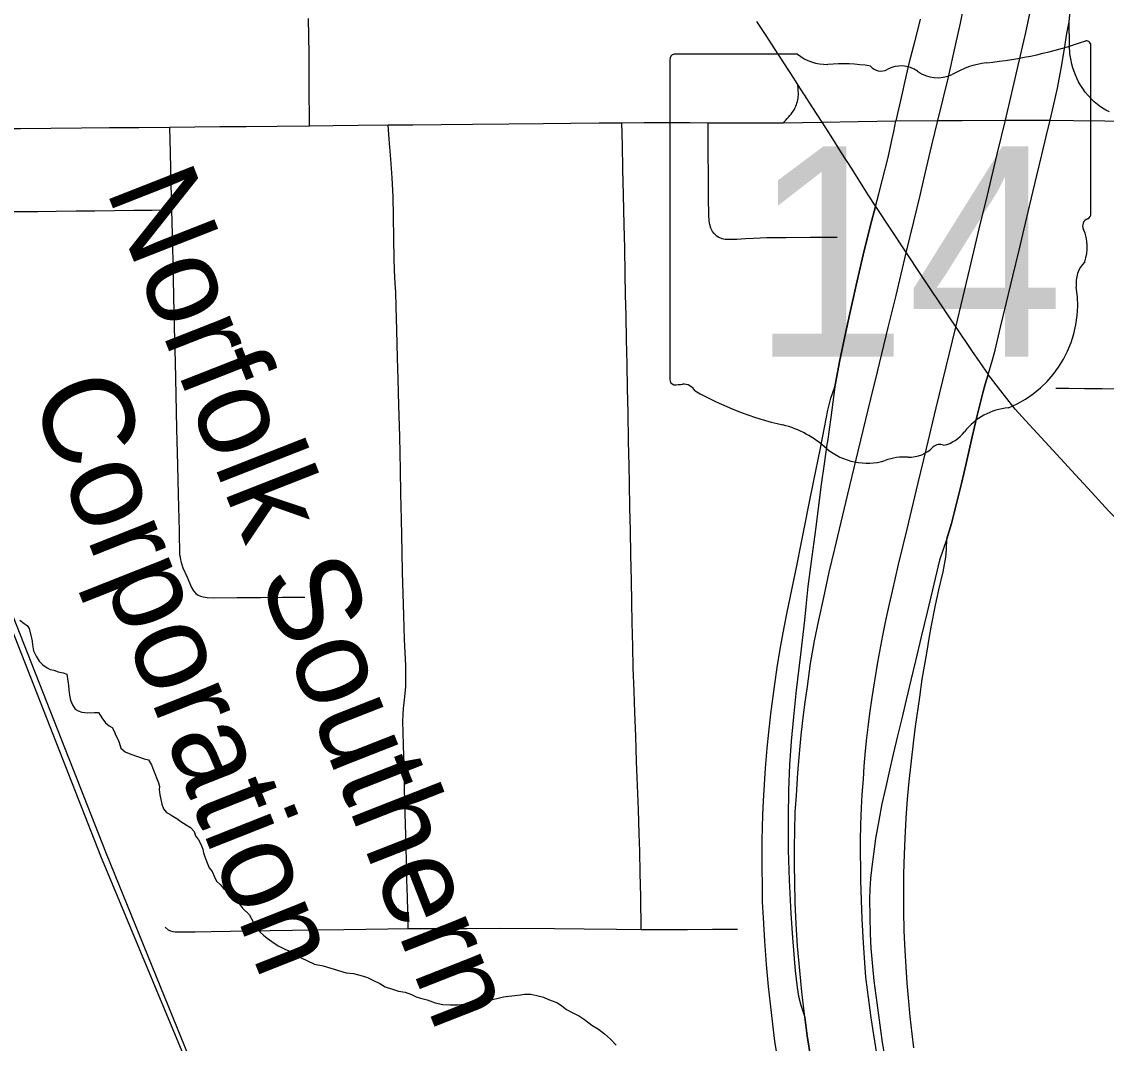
# Model space of a CAD drawing. Extents: x 0 to 34, y 0 to 22.
# Drawn here: x 4.679 to 5.359, y 16.317 to 16.957 of the extents above; entities that cross this region are included whole.
import ezdxf

# ---------------------------------------------------------------- set-up
doc = ezdxf.new("R2010")
doc.units = 0
for name, color, linetype in [('GM_X_City_Street', 7, 'Continuous'), ('GM_X_County_Road', 7, 'Continuous'), ('GM_X_Interchange_Ramps', 7, 'Continuous'), ('GM_X_Interstate_Route', 7, 'Continuous'), ('GM_X_Minor_River', 7, 'Continuous'), ('GM_X_Rail_Line', 7, 'Continuous'), ('GM_X_Rail_Line_Text', 7, 'Continuous'), ('GM_X_State_Location', 7, 'Continuous'), ('GM_X_State_Route', 7, 'Continuous'), ('GM_X_State_Shield', 7, 'Continuous')]:
    doc.layers.add(name, color=color, linetype=linetype)

msp = doc.modelspace()

# ---------------------------------------------------------------- linework, layer by layer
at = {"layer": 'GM_X_City_Street'}
for points in [[(4.85961, 16.892), (4.85946, 16.91777), (4.85928, 16.93707), (4.85899, 16.9591)], [(4.77844, 16.62273), (4.77808, 16.63813), (4.77755, 16.66072), (4.77711, 16.67929), (4.77657, 16.70219), (4.77608, 16.72351), (4.7756, 16.74388), (4.77509, 16.76552), (4.77463, 16.78504), (4.77411, 16.80709), (4.77372, 16.82388), (4.77336, 16.83936), (4.77296, 16.85565), (4.7725, 16.87506), (4.77212, 16.89111)], [(4.92138, 16.38902), (4.92111, 16.39977), (4.92089, 16.40863), (4.92061, 16.41963), (4.92036, 16.42948), (4.92005, 16.44149), (4.91973, 16.45434), (4.9194, 16.46773), (4.91913, 16.47813), (4.91879, 16.49176), (4.91848, 16.50384), (4.91827, 16.51213), (4.9181, 16.51875), (4.91818, 16.5233), (4.91841, 16.52691), (4.91879, 16.53054), (4.91949, 16.53631), (4.91987, 16.54061), (4.92003, 16.54308), (4.91987, 16.55386), (4.9191, 16.5701), (4.91864, 16.58511), (4.91826, 16.59896), (4.91787, 16.61213), (4.91756, 16.62498), (4.91715, 16.64561), (4.91689, 16.66139), (4.91664, 16.6764), (4.91608, 16.69726), (4.91553, 16.71665), (4.91507, 16.73313), (4.91469, 16.74667), (4.9142, 16.76399), (4.91392, 16.77862), (4.91361, 16.78763), (4.91331, 16.79324), (4.91292, 16.80133), (4.91271, 16.80902), (4.91247, 16.82096), (4.91216, 16.83565), (4.91192, 16.84735), (4.91131, 16.85936), (4.91054, 16.87098), (4.90957, 16.88361), (4.90889, 16.89249)], [(5.05672, 16.82998), (5.0563, 16.8486), (5.05592, 16.86468), (5.05557, 16.87983), (5.05525, 16.89386)], [(5.11425, 16.82315), (5.11297, 16.82444), (5.11209, 16.82565), (5.11098, 16.82778), (5.11024, 16.83006), (5.1099, 16.83243), (5.1097, 16.83588), (5.1096, 16.84691), (5.10949, 16.86102), (5.10937, 16.8748), (5.10929, 16.8849), (5.10921, 16.89391)], [(4.65945, 16.84522), (4.66116, 16.84357), (4.66256, 16.84246), (4.66455, 16.84116), (4.66614, 16.84033), (4.66778, 16.83964), (4.67005, 16.83892), (4.67238, 16.83844), (4.67475, 16.83823), (4.6894, 16.83831), (4.70088, 16.83846), (4.71347, 16.83861), (4.72509, 16.83875), (4.73754, 16.83891), (4.74961, 16.83906), (4.76101, 16.8392), (4.77336, 16.83936)], [(5.06729, 16.38837), (5.06716, 16.40913), (5.0668, 16.42372), (5.06646, 16.43762), (5.06611, 16.44837), (5.06556, 16.46374), (5.06502, 16.47868), (5.06447, 16.4938), (5.0639, 16.50962), (5.06336, 16.52447), (5.06288, 16.53775), (5.06236, 16.55243), (5.06207, 16.5658), (5.06175, 16.58083), (5.0615, 16.59333), (5.06121, 16.60739), (5.06089, 16.62303), (5.06058, 16.63859), (5.0603, 16.65257), (5.05999, 16.66812), (5.05977, 16.67886), (5.05946, 16.69433), (5.05909, 16.71242), (5.05879, 16.72719), (5.05848, 16.74283), (5.05818, 16.75794), (5.05787, 16.77306), (5.05761, 16.78608), (5.05735, 16.79928), (5.05702, 16.81526), (5.05672, 16.82998)], [(5.11425, 16.82315), (5.11594, 16.82208), (5.11788, 16.82131), (5.11994, 16.82091), (5.1222, 16.82083), (5.12722, 16.82103), (5.13257, 16.82129), (5.13772, 16.82156), (5.14608, 16.8219), (5.15785, 16.82198), (5.17323, 16.8221), (5.19016, 16.82223)], [(5.32708, 16.7276), (5.33521, 16.72751), (5.34491, 16.72741), (5.35616, 16.72729), (5.36721, 16.72717), (5.38138, 16.72703), (5.39772, 16.72685), (5.40803, 16.72698), (5.42057, 16.72712), (5.43305, 16.72727), (5.44573, 16.72742), (5.45746, 16.72756), (5.46798, 16.72768)], [(4.77844, 16.62273), (4.77874, 16.62012), (4.77913, 16.6183), (4.78031, 16.61497), (4.78294, 16.60912), (4.78578, 16.60278), (4.78704, 16.60073), (4.7884, 16.59903), (4.78982, 16.59795), (4.79124, 16.59724), (4.79298, 16.59677), (4.79559, 16.59645), (4.79963, 16.59629), (4.81411, 16.59639), (4.82884, 16.59648), (4.84245, 16.59657), (4.85677, 16.59661)], [(4.76921, 16.38999), (4.77114, 16.38822), (4.77255, 16.38753), (4.7739, 16.38718), (4.7755, 16.38695), (4.78801, 16.38704), (4.79802, 16.38719), (4.80985, 16.38737), (4.82308, 16.38756), (4.83491, 16.38774), (4.8489, 16.38795), (4.86317, 16.38816), (4.88109, 16.38843), (4.8948, 16.38863), (4.90857, 16.38884), (4.92138, 16.38902), (4.9406, 16.38909), (4.95829, 16.38916), (4.97831, 16.38922), (5.01304, 16.38912), (5.03168, 16.38886), (5.05192, 16.38858), (5.06729, 16.38837), (5.08164, 16.38845), (5.09631, 16.38853), (5.11209, 16.38862), (5.12762, 16.38871)]]:
    msp.add_lwpolyline(points, dxfattribs=at)
at = {"layer": 'GM_X_County_Road'}
for p, q in [((5.1114, 16.8939), (5.11249, 16.8939)), ((5.11249, 16.8939), (5.12712, 16.89388))]:
    msp.add_line(p, q, dxfattribs=at)
for points in [[(5.15618, 16.89385), (5.15799, 16.89555), (5.15886, 16.89645), (5.15969, 16.89737), (5.16049, 16.89833), (5.16126, 16.89931), (5.162, 16.90032), (5.1627, 16.90134), (5.16336, 16.9024), (5.1638, 16.90333), (5.1642, 16.90428), (5.16456, 16.90523), (5.16487, 16.90621), (5.16515, 16.9072), (5.16539, 16.9082), (5.16559, 16.9092), (5.16575, 16.91022), (5.16586, 16.91124), (5.16571, 16.91526), (5.16555, 16.91737)], [(5.1804, 16.8943), (5.20329, 16.89471), (5.22687, 16.89513), (5.25307, 16.8952), (5.26828, 16.8953), (5.29545, 16.89551), (5.3235, 16.89553), (5.3382, 16.89533), (5.3578, 16.89506), (5.37398, 16.89481)], [(5.21401, 16.84149), (5.21616, 16.84931), (5.21857, 16.85836), (5.22197, 16.87201), (5.22418, 16.88184), (5.22554, 16.88831), (5.22687, 16.89513)], [(5.28468, 16.7362), (5.28735, 16.74524), (5.28901, 16.7514), (5.29247, 16.76585), (5.29615, 16.78123), (5.30008, 16.79766), (5.30401, 16.81407), (5.30802, 16.83085), (5.31185, 16.84683), (5.31517, 16.86071), (5.3183, 16.87382), (5.32105, 16.8853), (5.3235, 16.89553)], [(4.63693, 16.88997), (4.64922, 16.89007), (4.66181, 16.89018), (4.67854, 16.89032), (4.69758, 16.89048), (4.71681, 16.89064), (4.7343, 16.89079), (4.75276, 16.89095), (4.77212, 16.89111), (4.78785, 16.89127), (4.80333, 16.89143), (4.81996, 16.8916), (4.83939, 16.89179), (4.85961, 16.892), (4.87448, 16.89215), (4.89015, 16.8923), (4.90889, 16.89249), (4.92428, 16.89263), (4.94206, 16.89278), (4.96177, 16.89295), (4.98437, 16.89315), (5.00615, 16.89333)], [(5.00615, 16.89333), (5.02331, 16.89352), (5.04109, 16.89371), (5.05525, 16.89386)], [(5.05525, 16.89386), (5.06926, 16.89395), (5.08426, 16.89405)], [(5.08426, 16.89405), (5.09792, 16.89397), (5.10921, 16.89391), (5.1114, 16.8939)], [(5.12712, 16.89388), (5.15618, 16.89385), (5.16829, 16.89408), (5.1804, 16.8943)], [(5.18872, 16.72834), (5.19154, 16.74411), (5.19491, 16.75995), (5.19804, 16.77434), (5.20193, 16.79218), (5.20642, 16.81118), (5.21091, 16.82971), (5.21401, 16.84149)], [(5.25874, 16.6331), (5.2617, 16.64275), (5.2649, 16.65533), (5.26786, 16.66782), (5.27082, 16.68042), (5.2747, 16.69703), (5.27762, 16.7096), (5.28128, 16.72462), (5.28287, 16.73019), (5.28468, 16.7362)], [(5.44332, 16.56415), (5.43321, 16.57486), (5.4175, 16.59153), (5.40615, 16.60347), (5.39451, 16.61552), (5.38365, 16.62677), (5.372, 16.63862), (5.36031, 16.65053), (5.34928, 16.66254), (5.33941, 16.67327), (5.32989, 16.68363), (5.32033, 16.69402), (5.31032, 16.70491), (5.30153, 16.71447), (5.29257, 16.72602), (5.28468, 16.7362)], [(5.1522, 16.31083), (5.1511, 16.31853), (5.14981, 16.32919), (5.14823, 16.34183), (5.1471, 16.35282), (5.1458, 16.36658), (5.1447, 16.38107), (5.14385, 16.39574), (5.1434, 16.40585), (5.14327, 16.41411), (5.14313, 16.42878), (5.14319, 16.44452), (5.14352, 16.46023), (5.14387, 16.46912), (5.14449, 16.47932), (5.14522, 16.48962), (5.14627, 16.50212), (5.14722, 16.51212), (5.14851, 16.52351), (5.15076, 16.54073), (5.15271, 16.5541), (5.15483, 16.56644), (5.15686, 16.57769), (5.15878, 16.58734), (5.16161, 16.60133), (5.16493, 16.61737), (5.16726, 16.62907), (5.16962, 16.64053), (5.17258, 16.65527), (5.17547, 16.66965), (5.17936, 16.68887), (5.18212, 16.7029), (5.18424, 16.71373), (5.18619, 16.72133), (5.18872, 16.72834)], [(5.24794, 16.57212), (5.2489, 16.57787), (5.25161, 16.59159), (5.25384, 16.60132), (5.25638, 16.61253), (5.25815, 16.62168), (5.25865, 16.62651), (5.25874, 16.6331)], [(5.23816, 16.31434), (5.23713, 16.32318), (5.2358, 16.33407), (5.23477, 16.34558), (5.23399, 16.35482), (5.23324, 16.36511), (5.23264, 16.37535), (5.23213, 16.38766), (5.23183, 16.40023), (5.23174, 16.41125), (5.23188, 16.42341), (5.23232, 16.43575), (5.23259, 16.44558), (5.23333, 16.45815), (5.23418, 16.47018), (5.2352, 16.48109), (5.23784, 16.50521), (5.23916, 16.51562), (5.24176, 16.53411), (5.24342, 16.54519), (5.24619, 16.56159), (5.24794, 16.57212)]]:
    msp.add_lwpolyline(points, dxfattribs=at)
at = {"layer": 'GM_X_Interchange_Ramps'}
for points in [[(5.36058, 16.90066), (5.35839, 16.9018), (5.35628, 16.90308), (5.35426, 16.90449), (5.35115, 16.90703), (5.34914, 16.90894), (5.34724, 16.91096), (5.34547, 16.9131), (5.34388, 16.91524), (5.34248, 16.91736), (5.34122, 16.91957), (5.34011, 16.92185), (5.33914, 16.9242), (5.33778, 16.9282), (5.3371, 16.93062), (5.33634, 16.93384), (5.33576, 16.93709), (5.33563, 16.9423), (5.33533, 16.95712), (5.33639, 16.96769)], [(5.24212, 16.9588), (5.23869, 16.94524), (5.235, 16.93092), (5.23236, 16.91917), (5.23076, 16.91236), (5.22687, 16.89513)], [(5.3235, 16.89553), (5.32558, 16.90454), (5.3281, 16.91547), (5.33038, 16.92785), (5.33244, 16.9401), (5.33388, 16.94967), (5.33533, 16.95712)]]:
    msp.add_lwpolyline(points, dxfattribs=at)
at = {"layer": 'GM_X_Interstate_Route'}
for points in [[(5.29545, 16.89551), (5.30213, 16.92435), (5.30819, 16.95048), (5.31108, 16.96422), (5.31407, 16.97888), (5.3149, 16.98299), (5.31828, 17.00054), (5.32159, 17.01927), (5.32574, 17.03919), (5.32824, 17.0537), (5.33054, 17.06705), (5.33447, 17.09205), (5.33892, 17.12036), (5.34177, 17.14162), (5.34402, 17.16274), (5.34671, 17.1852), (5.34971, 17.21471), (5.35188, 17.23585), (5.35248, 17.24377), (5.35462, 17.26874), (5.35621, 17.28915), (5.35803, 17.31057), (5.35957, 17.32645)], [(5.25307, 16.8952), (5.25651, 16.90881), (5.25957, 16.92162), (5.26451, 16.94327), (5.26737, 16.95624), (5.27278, 16.98323)], [(5.16983, 16.33364), (5.16794, 16.34946), (5.16661, 16.36275), (5.16528, 16.37798), (5.16431, 16.39205), (5.16387, 16.40516), (5.1636, 16.41835), (5.16342, 16.42853), (5.16333, 16.44022), (5.1636, 16.45032), (5.16387, 16.46192), (5.16466, 16.47236), (5.16555, 16.48662), (5.1667, 16.50105), (5.1675, 16.51026), (5.16891, 16.52301), (5.16998, 16.5308), (5.17148, 16.54063), (5.17343, 16.55515), (5.17591, 16.56923), (5.17865, 16.58225), (5.18166, 16.59651), (5.18512, 16.61226), (5.18866, 16.62702), (5.19551, 16.65595), (5.20318, 16.68818), (5.21109, 16.72088), (5.21529, 16.73789), (5.2221, 16.76553), (5.22705, 16.78561), (5.23339, 16.81228), (5.2381, 16.8321), (5.24177, 16.84754), (5.24522, 16.86205), (5.24943, 16.8798), (5.25307, 16.8952)], [(5.21532, 16.30784), (5.21138, 16.33306), (5.20906, 16.35077), (5.20814, 16.35869), (5.2074, 16.36763), (5.20657, 16.38016), (5.20584, 16.39499), (5.20528, 16.40678), (5.20501, 16.41912), (5.20472, 16.44405), (5.20488, 16.45429), (5.20538, 16.46465), (5.20581, 16.47311), (5.20651, 16.48273), (5.20702, 16.49076), (5.20792, 16.50049), (5.20872, 16.50855), (5.20946, 16.51528), (5.21059, 16.52381), (5.21197, 16.53387), (5.21358, 16.54429), (5.21562, 16.55602), (5.21675, 16.56263), (5.21861, 16.57263), (5.2206, 16.58199), (5.22269, 16.59136), (5.22466, 16.60032), (5.22859, 16.61702), (5.23393, 16.63928), (5.24088, 16.66821), (5.24605, 16.68974), (5.25217, 16.71523), (5.25835, 16.74095), (5.26433, 16.76586), (5.27314, 16.80257), (5.2791, 16.8274), (5.28419, 16.84857), (5.29032, 16.87412), (5.29545, 16.89551)], [(5.24429, 16.04606), (5.24089, 16.05746), (5.2372, 16.06981), (5.23363, 16.08179), (5.22891, 16.09762), (5.22527, 16.10981), (5.22087, 16.12457), (5.21663, 16.13875), (5.21044, 16.16009), (5.20334, 16.18532), (5.19707, 16.20667), (5.19052, 16.23022), (5.18485, 16.25253), (5.18131, 16.26856), (5.17767, 16.28467), (5.17555, 16.29574), (5.17352, 16.30761), (5.17136, 16.32184), (5.16983, 16.33364)]]:
    msp.add_lwpolyline(points, dxfattribs=at)
at = {"layer": 'GM_X_Minor_River'}
for points in [[(4.67822, 16.58232), (4.6809, 16.58007), (4.68282, 16.57895), (4.68398, 16.57707), (4.68557, 16.571), (4.68598, 16.56911), (4.68601, 16.56683), (4.68682, 16.56303), (4.68838, 16.55963), (4.69032, 16.55661), (4.69262, 16.55436), (4.6953, 16.55249), (4.69721, 16.55137), (4.6995, 16.55102), (4.70217, 16.54992), (4.70521, 16.54919), (4.7075, 16.54846), (4.70831, 16.54429), (4.70873, 16.54125), (4.70877, 16.53859), (4.70919, 16.53517), (4.70999, 16.53214), (4.71116, 16.52911), (4.71272, 16.52647), (4.71463, 16.52536), (4.71692, 16.52462), (4.72071, 16.52429), (4.72489, 16.52434), (4.72754, 16.52438), (4.72949, 16.52098), (4.7318, 16.51797), (4.7341, 16.5161), (4.73602, 16.51498), (4.73718, 16.51271), (4.73835, 16.51006), (4.73952, 16.5078), (4.74031, 16.50553), (4.7415, 16.50212), (4.74418, 16.49987), (4.74762, 16.49839), (4.75181, 16.49692), (4.756, 16.49546), (4.75867, 16.49473), (4.7606, 16.49171), (4.76179, 16.4883), (4.76493, 16.48036), (4.76571, 16.47808), (4.76536, 16.47618), (4.76578, 16.47276), (4.76619, 16.47087), (4.767, 16.46707), (4.76817, 16.46404), (4.7701, 16.46179), (4.77201, 16.46067), (4.77393, 16.45955), (4.7766, 16.45807), (4.7789, 16.45619), (4.78235, 16.45396), (4.78502, 16.45247), (4.78733, 16.44984), (4.78813, 16.44718), (4.79006, 16.44455), (4.79161, 16.4419), (4.79279, 16.43888), (4.7932, 16.4366), (4.79399, 16.43395), (4.79556, 16.43017), (4.79674, 16.42714), (4.79866, 16.42488), (4.79984, 16.42185), (4.8014, 16.41883), (4.8037, 16.41658), (4.80601, 16.41394), (4.80831, 16.41245), (4.81022, 16.41172), (4.81369, 16.4072)], [(4.81369, 16.4072), (4.81756, 16.40192), (4.82178, 16.39779), (4.8245, 16.39288), (4.82683, 16.38911), (4.82876, 16.38685), (4.83068, 16.38497), (4.83298, 16.3831), (4.83604, 16.38086), (4.83987, 16.37825), (4.84446, 16.37602), (4.84827, 16.37455), (4.85172, 16.37193), (4.85783, 16.36897), (4.86279, 16.36675), (4.86812, 16.36567), (4.8826, 16.36129), (4.88715, 16.36097), (4.89249, 16.35952), (4.89592, 16.35842), (4.89973, 16.35657), (4.90355, 16.35472), (4.907, 16.35248), (4.91157, 16.35101), (4.91538, 16.34992), (4.91956, 16.34922), (4.92338, 16.34774), (4.92643, 16.34626), (4.9291, 16.34553), (4.93329, 16.34444), (4.93824, 16.34261), (4.94319, 16.34153), (4.94775, 16.34121), (4.9523, 16.34126), (4.95685, 16.3417), (4.95989, 16.34174), (4.96178, 16.34176), (4.96443, 16.34256), (4.96746, 16.34298), (4.97087, 16.3434), (4.97427, 16.34459), (4.97768, 16.34539), (4.98108, 16.34619), (4.98449, 16.34662), (4.98828, 16.34705), (4.99169, 16.34747), (4.99434, 16.34788), (4.99813, 16.34793), (5.00194, 16.34722), (5.00613, 16.34613), (5.00918, 16.34465), (5.01223, 16.34355), (5.0149, 16.34244), (5.01759, 16.34058), (5.02065, 16.33833), (5.02409, 16.33647), (5.02867, 16.33425), (5.03174, 16.33201), (5.03634, 16.32864), (5.04054, 16.32603), (5.04438, 16.32304), (5.04821, 16.31967), (5.05168, 16.31591)]]:
    msp.add_lwpolyline(points, dxfattribs=at)
at = {"layer": 'GM_X_Rail_Line'}
for points in [[(4.94786, 15.88471), (4.90848, 15.98736), (4.79437, 16.27699), (4.72896, 16.43441), (4.66097, 16.60712), (4.63502, 16.67462), (4.57662, 16.82073), (4.49771, 17.02098), (4.4404, 17.16588), (4.37365, 17.33387), (4.30764, 17.5026), (4.24561, 17.66066)], [(4.95452, 15.87746), (4.9091, 15.99294), (4.79747, 16.2761), (4.73244, 16.43577), (4.66446, 16.60847), (4.6385, 16.67598), (4.58009, 16.8221), (4.50119, 17.02234), (4.44387, 17.16725), (4.37713, 17.33523), (4.31112, 17.50396), (4.24909, 17.66202)]]:
    msp.add_lwpolyline(points, dxfattribs=at)
at = {"layer": 'GM_X_State_Route'}
msp.add_line((5.20934, 16.8488), (5.21401, 16.84149), dxfattribs=at)
for points in [[(5.13966, 16.95726), (5.14498, 16.94913), (5.151, 16.93981), (5.15376, 16.93557)], [(5.15376, 16.93557), (5.15653, 16.93132), (5.16267, 16.92185), (5.16382, 16.92006)], [(5.16382, 16.92006), (5.16555, 16.91737), (5.16888, 16.91217), (5.16942, 16.91133)], [(5.16942, 16.91133), (5.1743, 16.90374), (5.1804, 16.8943)], [(5.1804, 16.8943), (5.18604, 16.88541), (5.19269, 16.87495), (5.19919, 16.86472)], [(5.19919, 16.86472), (5.20623, 16.85367), (5.20934, 16.8488)], [(5.21401, 16.84149), (5.21091, 16.82971), (5.20642, 16.81118), (5.20193, 16.79218), (5.19804, 16.77434), (5.19491, 16.75995), (5.19154, 16.74411), (5.18872, 16.72834)], [(5.21401, 16.84149), (5.22356, 16.82725), (5.23339, 16.81228), (5.24227, 16.79876), (5.26005, 16.77218), (5.26433, 16.76586), (5.27427, 16.75116), (5.28468, 16.7362)], [(5.28468, 16.7362), (5.28287, 16.73019), (5.28128, 16.72462), (5.27762, 16.7096), (5.2747, 16.69703), (5.27082, 16.68042), (5.26786, 16.66782), (5.2649, 16.65533), (5.2617, 16.64275), (5.25874, 16.6331)], [(5.18872, 16.72834), (5.18611, 16.70911), (5.184, 16.69419)], [(5.184, 16.69419), (5.18371, 16.6922), (5.18198, 16.68025), (5.18009, 16.66714), (5.17867, 16.65574), (5.17666, 16.6405), (5.17424, 16.62216), (5.17176, 16.6033), (5.17043, 16.5909), (5.16955, 16.58231), (5.16715, 16.56071), (5.1645, 16.5383), (5.16428, 16.53636)], [(5.25874, 16.6331), (5.25423, 16.61975), (5.24982, 16.60129), (5.24647, 16.5873), (5.24279, 16.57189), (5.2392, 16.55688), (5.23629, 16.54468), (5.23323, 16.53234), (5.23049, 16.52062), (5.22794, 16.50979), (5.22518, 16.49827), (5.22283, 16.4882), (5.22048, 16.47792), (5.21813, 16.46719), (5.21611, 16.45679), (5.21408, 16.4454), (5.21277, 16.43566), (5.21173, 16.42771), (5.21097, 16.42039), (5.21049, 16.41369), (5.21028, 16.40747), (5.21068, 16.38576), (5.21125, 16.37672), (5.21215, 16.36533), (5.21304, 16.35641), (5.21484, 16.34252), (5.21829, 16.31758), (5.2223, 16.29547)], [(5.16428, 16.53636), (5.16264, 16.52175), (5.16122, 16.50652), (5.1603, 16.49165), (5.15964, 16.47585), (5.15933, 16.45868), (5.15949, 16.43826), (5.16004, 16.41935), (5.16099, 16.39854), (5.16202, 16.38334), (5.16376, 16.36261), (5.16494, 16.35218), (5.1659, 16.34662), (5.16727, 16.34107), (5.16983, 16.33364)], [(5.16983, 16.33364), (5.17136, 16.32184), (5.17352, 16.30761), (5.17555, 16.29574), (5.17767, 16.28467), (5.18131, 16.26856), (5.18485, 16.25253), (5.19052, 16.23022), (5.19707, 16.20667), (5.20334, 16.18532), (5.21044, 16.16009), (5.21663, 16.13875), (5.22087, 16.12457), (5.22527, 16.10981), (5.22891, 16.09762), (5.23363, 16.08179), (5.2372, 16.06981), (5.24089, 16.05746), (5.24429, 16.04606)]]:
    msp.add_lwpolyline(points, dxfattribs=at)
at = {"layer": 'GM_X_State_Shield'}
for p, q in [((5.1652, 16.93679), (5.08798, 16.93679)), ((5.34905, 16.83706), (5.34905, 16.94175)), ((5.08538, 16.93335), (5.08538, 16.73323)), ((5.34902, 16.83709), (5.34905, 16.83706))]:
    msp.add_line(p, q, dxfattribs=at)
for centre, radius, start, end in [((5.25513, 17.20962), 0.27962, 275.84447, 288.90645), ((5.34613, 16.94218), 0.00294, 351.86209, 97.738), ((5.0884, 16.93377), 0.00305, 98.1301, 188.1301), ((5.18358, 16.96002), 0.02963, 231.61951, 271.11188), ((5.19341, 16.82444), 0.10636, 80.48669, 94.98827), ((5.21755, 16.93481), 0.00855, 219.79206, 297.10237), ((5.2301, 16.91168), 0.01777, 54.46668, 119.14113), ((5.29079, 16.87567), 0.05625, 97.34618, 120.76885), ((5.25304, 16.9434), 0.02138, 233.85621, 294.82819), ((5.34837, 16.82938), 0.00454, 107.94398, 210.33697), ((5.34592, 16.83666), 0.00314, 289.60381, 7.73413), ((5.31947, 16.81614), 0.02727, 340.03296, 23.64957), ((5.35957, 16.79325), 0.01984, 136.8065, 186.92959), ((5.27079, 16.77994), 0.06994, 292.30889, 8.98584), ((5.08843, 16.73279), 0.00308, 171.95839, 258.30661), ((5.0889, 16.75326), 0.02352, 267.33899, 280.60386), ((5.09371, 16.72168), 0.00848, 29.74838, 93.27175), ((5.20077, 16.90148), 0.20192, 240.41292, 257.1985), ((5.30028, 16.67704), 0.0383, 94.40312, 142.57675), ((5.14057, 16.64332), 0.06318, 47.18416, 75.83597), ((5.25175, 16.71383), 0.0226, 282.87319, 323.27711), ((5.25431, 16.68632), 0.00601, 65.75173, 132.64842), ((5.2089, 16.72069), 0.04009, 230.70037, 286.29184), ((5.23206, 16.6515), 0.03294, 85.69512, 111.20995), ((5.23499, 16.7057), 0.02136, 268.77702, 315.54927)]:
    msp.add_arc(centre, radius, start, end, dxfattribs=at)

# ---------------------------------------------------------------- texts
at = {"layer": 'GM_X_Rail_Line_Text'}
for s, rotation, p in [('Norfolk Southern', 291.44766, (4.73191, 16.85191)), ('Corporation', 291.60307, (4.68427, 16.72374))]:
    msp.add_text(s, height=0.0566288, rotation=rotation, dxfattribs=at).set_placement(p)
at = {"layer": 'GM_X_State_Location'}
for s, p in [('s', (5.21425, 16.81998)), ('r', (5.21424, 16.81998))]:
    msp.add_text(s, height=0.000189, dxfattribs=at).set_placement(p)
msp.add_text('14', height=0.000189, rotation=0.00001, dxfattribs=at).set_placement((5.16655, 16.8062))
at = {"layer": 'GM_X_State_Shield'}
msp.add_text('14', height=0.131836, dxfattribs=at).set_placement((5.13597, 16.74734))

doc.saveas('drawing.dxf')
